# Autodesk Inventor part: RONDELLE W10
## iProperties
Created: 2004-11
Part Number: RONDELLE W10
Document SubType Name: Modeling
Designer: Bruno
Manufacturer: Standard
Standards Organization: Custom
Author: Bruno
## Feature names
1. Base1
